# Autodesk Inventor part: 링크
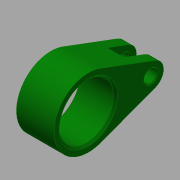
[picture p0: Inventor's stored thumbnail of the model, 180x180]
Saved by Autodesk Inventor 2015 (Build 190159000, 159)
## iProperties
Created: 2016-08
Part Number: 링크
Material: 강철, 탄소
Document SubType Name: Modeling
Designer: mduedu
Density: 7.87 g/cm^3
Appearance: 진녹색
Author: mduedu
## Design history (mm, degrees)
sketch "스케치1"
  geometry: L1 (32.1, 5.62)-(5.775, 15.456); L2 (32.1, -5.62)-(5.775, -15.456); C1 r 13 at (0, 0); C2 r 3 at (30, 0); A1 r 16.5 centre (0, 0) between (5.775, 15.456) and (5.775, -15.456); A2 r 6 centre (30, 0) between (32.1, 5.62) and (32.1, -5.62); 1 further point
  constraints: 4 centre point, 4 end point, 4 point on circle, 4 tangent, 3 coincident, 1 horizontal alignment
  dimensions: "d0" = 33 diameter of A1; "d2" = 12 diameter of A2; "d3" = 30 distance of A2.centre point (0, 0); "d4" = 26 diameter of C1; "d5" = 6 diameter of C2
extrude "돌출1" new body sketch "스케치1" stored distance "d6" = 18; taper "d7" = 0 deg
sketch "스케치2"
  geometry: L1 (-9, 36)-(9, 36) reference; L2 (0, 0)-(0, 36); L3 (-4, 36)-(4, 36); L4 (4, 36)-(4, 22); L5 (4, 22)-(-4, 22); L6 (-4, 22)-(-4, 36)
  constraints: 10 end point, 2 midpoint, 2 parallel, 1 horizontal, 1 perpendicular, 1 point on line
  dimensions: "d8" = 8 distance between parallel lines of L4 L6; "d10" = 14 distance of L3.end L4.end
extrude "돌출2" cut sketch "스케치2" stored distance "d11" = 20; taper "d12" = 0 deg
chamfer "모따기1" distance "d13" = 1; stored, may be unused: second distance "d14" = 2, angle "d15" = 45 deg
chamfer "모따기2" distance "d16" = 0.5; stored, may be unused: second distance "d17" = 2, angle "d18" = 45 deg
node "솔리드1"
